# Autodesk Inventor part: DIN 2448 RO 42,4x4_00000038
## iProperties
Created: 2006-02
Part Number: DIN 2448 RO 42,4x4_00000038
Material: Default
Document SubType Name: Modeling
Designer: FranzK
Stock Number: DIN 2448 RO 42,4x4
Mass: 151.597 g
Surface Area: 767.637 cm^2
Volume: 151.597 cm^3
Density: 1 g/cm^3
G_L: 314.159 mm
G_W: 42.400 mm
G_H: 42.400 mm
AFG_Item: 42.4 x 4
CSToolsMass: 0.2
CSToolsVolume: 151597.0
CSToolsArea: 768.0
Author: FranzK
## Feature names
1. AFG_Detailed_DIN 2448 RO 42,4x4_00000038
2. AFG_Simplified_DIN 2448 RO 42,4x4_00000038
